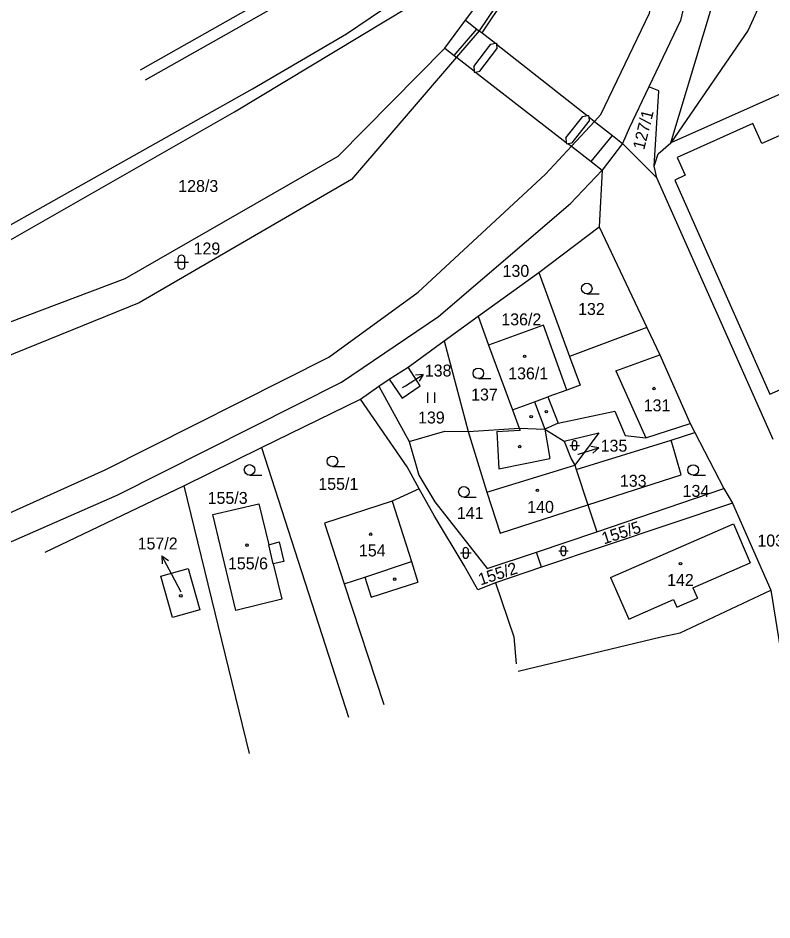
# Model space of a CAD drawing. Extents: x -783716 to -783033, y -1065203 to -1064697.
# Drawn here: x -783577.2 to -783469.9, y -1065203.3 to -1065075 of the extents above; entities that cross this region are included whole.
import ezdxf

# ---------------------------------------------------------------- set-up
doc = ezdxf.new("R2010")
doc.units = 0
for name, color, linetype in [('Budovy', 7, 'Continuous'), ('Doplňkové značky', 7, 'Continuous'), ('Doplňující texty', 7, 'Continuous'), ('Kultury', 7, 'Continuous'), ('Stromy_porost', 7, 'Continuous'), ('Značky IS', 7, 'Continuous')]:
    doc.layers.add(name, color=color, linetype=linetype)

msp = doc.modelspace()

# ---------------------------------------------------------------- linework, layer by layer
at = {"layer": 'Budovy'}
for p, q in [((-783540.15, -1065071.29), (-783559.84, -1065082.45)), ((-783482.97, -1065075.36), (-783487.46, -1065084.8)), ((-783455.41, -1065079.83), (-783484.32, -1065092.79)), ((-783487.46, -1065084.8), (-783490.25, -1065090.68)), ((-783490.25, -1065090.68), (-783491.22, -1065092.86)), ((-783491.22, -1065092.86), (-783494.09, -1065096.67)), ((-783486.32, -1065097.76), (-783491.22, -1065092.86)), ((-783486.32, -1065097.76), (-783486.71, -1065096.08)), ((-783494.09, -1065096.67), (-783494.53, -1065104.73)), ((-783469.78, -1065134.96), (-783486.32, -1065097.76)), ((-783503.12, -1065111.2), (-783494.53, -1065104.73)), ((-783494.53, -1065104.73), (-783487.76, -1065119.02)), ((-783511.74, -1065117.43), (-783503.12, -1065111.2)), ((-783503.12, -1065111.2), (-783498.74, -1065123.15)), ((-783516.56, -1065120.92), (-783511.74, -1065117.43)), ((-783511.74, -1065117.43), (-783510.28, -1065121.53)), ((-783487.76, -1065119.02), (-783498.74, -1065123.15)), ((-783521.71, -1065124.69), (-783516.56, -1065120.92)), ((-783516.56, -1065120.92), (-783513.18, -1065133.85)), ((-783524.38, -1065126.39), (-783521.71, -1065124.69)), ((-783525.85, -1065127.4), (-783524.38, -1065126.39)), ((-783528.47, -1065129.21), (-783525.85, -1065127.4)), ((-783525.85, -1065127.4), (-783521.55, -1065135.25)), ((-783542.54, -1065136.12), (-783528.47, -1065129.21)), ((-783513.18, -1065133.85), (-783505.89, -1065133.34)), ((-783505.89, -1065133.34), (-783502.25, -1065133.52)), ((-783500.34, -1065132.66), (-783502.25, -1065133.52)), ((-783481.58, -1065132.68), (-783480.9, -1065133.99)), ((-783502.25, -1065133.52), (-783499.53, -1065135.19)), ((-783480.9, -1065133.99), (-783476.78, -1065141.96)), ((-783553.59, -1065141.54), (-783542.54, -1065136.12)), ((-783542.54, -1065136.12), (-783530.17, -1065174.45)), ((-783573.32, -1065150.99), (-783553.59, -1065141.54)), ((-783553.59, -1065141.54), (-783544.3, -1065179.62)), ((-783494.85, -1065148.08), (-783476.78, -1065141.96)), ((-783476.78, -1065141.96), (-783475.54, -1065144.01)), ((-783475.54, -1065144.01), (-783502.74, -1065153.14)), ((-783496.14, -1065144.24), (-783494.85, -1065148.08)), ((-783475.54, -1065144.01), (-783470.12, -1065156.38)), ((-783503.46, -1065150.98), (-783494.85, -1065148.08)), ((-783502.74, -1065153.14), (-783503.46, -1065150.98)), ((-783502.74, -1065153.14), (-783509.29, -1065155.34))]:
    msp.add_line(p, q, dxfattribs=at)
for points in [[(-783586.68, -1065149.16), (-783564.78, -1065139.29), (-783532.97, -1065123.26), (-783520.29, -1065114.03), (-783502.16, -1065097.24), (-783498.48, -1065093.26), (-783495.21, -1065089.71), (-783494.31, -1065088.74), (-783487.35, -1065074.33), (-783482.56, -1065054.25), (-783479.58, -1065017.78), (-783475.47, -1064981.45), (-783469.34, -1064952.28), (-783461.55, -1064937.01), (-783445.96, -1064920.48), (-783433.11, -1064911.15), (-783418.04, -1064903.77), (-783403.59, -1064898.67), (-783393.97, -1064894.19), (-783364.93, -1064886.92), (-783332.97, -1064881.2)], [(-783416.55, -1064908), (-783430.48, -1064914.8), (-783443.35, -1064924.13), (-783457.58, -1064939.04), (-783464.9, -1064953.22), (-783471.03, -1064982.39), (-783475.1, -1065018.21), (-783477.98, -1065052.91), (-783478.07, -1065054.51), (-783482.97, -1065075.36)], [(-783607.85, -1065123.43), (-783546.39, -1065088.37), (-783521.44, -1065073.34), (-783511.77, -1065063.08), (-783506.35, -1065048.95), (-783502.14, -1065032.55), (-783497.09, -1065007.24), (-783492.53, -1064987.86)], [(-783484.32, -1065092.79), (-783477.5, -1065070.05), (-783471.02, -1065037.32)], [(-783467.47, -1065050.82), (-783467.56, -1065063.94), (-783473.33, -1065076.72), (-783484.32, -1065092.79)], [(-783504.59, -1065066.42), (-783511.59, -1065076.83), (-783514.83, -1065080.59), (-783529.78, -1065097.96), (-783559.97, -1065115.54), (-783579.36, -1065123.41), (-783592.85, -1065128.61), (-783597.17, -1065129.64), (-783598.62, -1065130.29), (-783638.54, -1065148.19)], [(-783580.95, -1065119.21), (-783561.96, -1065112.08), (-783531.67, -1065094.68), (-783516.49, -1065079.31), (-783513.55, -1065075.3), (-783512.37, -1065073.74), (-783504.59, -1065066.42)], [(-783486.71, -1065096.08), (-783486.05, -1065085.37), (-783487.46, -1065084.8)], [(-783453.34, -1065084.82), (-783463.36, -1065089.28), (-783464.48, -1065086.76), (-783468.77, -1065088.67), (-783467.65, -1065091.19), (-783471.41, -1065092.87), (-783472.69, -1065090.02), (-783483.45, -1065094.84), (-783482.3, -1065097.39), (-783483.76, -1065098.09), (-783470.24, -1065128.54), (-783467.23, -1065127.21), (-783466.55, -1065128.54), (-783460.33, -1065125.81), (-783460.98, -1065124.44), (-783457.93, -1065123.1), (-783461.31, -1065115.7), (-783433.81, -1065103.48), (-783436.82, -1065096.73), (-783436.47, -1065096.56)], [(-783486.71, -1065096.08), (-783486.12, -1065094.34), (-783484.32, -1065092.79)], [(-783714.74, -1065203.31), (-783709.33, -1065202.33), (-783678.96, -1065185.72), (-783654.5, -1065174.91), (-783629.71, -1065165.76), (-783589.13, -1065151.92), (-783581.73, -1065151.06), (-783562.99, -1065142.86), (-783531.18, -1065126.83), (-783517.38, -1065117.45), (-783498.6, -1065101.42), (-783494.09, -1065096.67)], [(-783499.13, -1065127.94), (-783502.45, -1065118.68), (-783510.28, -1065121.53)], [(-783487.76, -1065119.02), (-783485.91, -1065122.94), (-783481.58, -1065132.68)], [(-783510.28, -1065121.53), (-783506.84, -1065130.77), (-783505.89, -1065133.34)], [(-783498.74, -1065123.15), (-783497.24, -1065127.25), (-783499.13, -1065127.94)], [(-783524.38, -1065126.39), (-783522.56, -1065129.07), (-783520.01, -1065127.35), (-783521.71, -1065124.69)], [(-783499.13, -1065127.94), (-783501.84, -1065128.92), (-783500.34, -1065132.66)], [(-783520.12, -1065141.97), (-783521.86, -1065138.86), (-783528.47, -1065129.21)], [(-783500.34, -1065132.66), (-783492.31, -1065130.95), (-783490.82, -1065134.42), (-783487.88, -1065134.73), (-783481.58, -1065132.68)], [(-783521.55, -1065135.25), (-783516.5, -1065133.78), (-783513.18, -1065133.85)], [(-783513.18, -1065133.85), (-783510.53, -1065142.48), (-783508.62, -1065148.28), (-783496.14, -1065144.24)], [(-783499.53, -1065135.19), (-783494.6, -1065134), (-783497.98, -1065138.64)], [(-783496.14, -1065144.24), (-783482.86, -1065140), (-783484.28, -1065135.07), (-783480.9, -1065133.99)], [(-783521.55, -1065135.25), (-783520.17, -1065140.02), (-783517.91, -1065143.82), (-783510.44, -1065153.34), (-783503.46, -1065150.98)], [(-783499.53, -1065135.19), (-783498.49, -1065137.72), (-783497.98, -1065138.64)], [(-783497.98, -1065138.64), (-783497.82, -1065139.25), (-783496.14, -1065144.24)], [(-783520.12, -1065141.97), (-783523.98, -1065143.75), (-783533.59, -1065146.88), (-783530.8, -1065155.52), (-783525.15, -1065172.66)], [(-783509.29, -1065155.34), (-783511.8, -1065156.37), (-783513.75, -1065152.91), (-783517.96, -1065145.89), (-783520.12, -1065141.97)], [(-783539.37, -1065152.31), (-783540.88, -1065152.66), (-783539.67, -1065157.7), (-783546.23, -1065159.28), (-783549.48, -1065145.64), (-783542.92, -1065144.1), (-783541.52, -1065149.95), (-783540.06, -1065149.52), (-783539.37, -1065152.31)], [(-783552.99, -1065153.33), (-783551.32, -1065159.2), (-783555.21, -1065160.31), (-783556.86, -1065154.43), (-783552.99, -1065153.33)], [(-783509.29, -1065155.34), (-783506.65, -1065163.02), (-783506.34, -1065166.89)], [(-783506.07, -1065167.92), (-783485.73, -1065163.03), (-783483, -1065162.45), (-783470.12, -1065156.38)], [(-783470.12, -1065156.38), (-783468.61, -1065165.85), (-783468.3, -1065170.76)]]:
    msp.add_lwpolyline(points, dxfattribs=at)
at = {"layer": 'Doplňkové značky'}
for p, q in [((-783547.52, -1065077.32), (-783528.48, -1065066.44)), ((-783511.17, -1065077.1), (-783504.11, -1065066.56)), ((-783530.49, -1065077.27), (-783523.72, -1065072.69)), ((-783513.55, -1065075.3), (-783511.91, -1065076.58)), ((-783515.16, -1065080.33), (-783511.91, -1065076.58)), ((-783511.91, -1065076.58), (-783511.59, -1065076.83)), ((-783511.59, -1065076.83), (-783511.17, -1065077.1)), ((-783559.07, -1065083.82), (-783547.52, -1065077.32)), ((-783543.86, -1065085.11), (-783530.49, -1065077.27)), ((-783511.17, -1065077.1), (-783509.28, -1065078.6)), ((-783516.49, -1065079.31), (-783515.16, -1065080.33)), ((-783512.38, -1065081.91), (-783509.94, -1065078.71)), ((-783511.51, -1065082.59), (-783509.07, -1065079.39)), ((-783509.94, -1065078.71), (-783509.28, -1065078.6)), ((-783509.28, -1065078.6), (-783509.13, -1065078.57)), ((-783509.13, -1065078.57), (-783509.12, -1065078.72)), ((-783509.12, -1065078.72), (-783496.23, -1065088.9)), ((-783509.12, -1065078.72), (-783509.07, -1065079.39)), ((-783515.16, -1065080.33), (-783514.83, -1065080.59)), ((-783514.83, -1065080.59), (-783512.33, -1065082.53)), ((-783512.38, -1065081.91), (-783512.33, -1065082.53)), ((-783512.33, -1065082.53), (-783512.31, -1065082.73)), ((-783512.31, -1065082.73), (-783512.11, -1065082.7)), ((-783512.11, -1065082.7), (-783511.51, -1065082.59)), ((-783512.11, -1065082.7), (-783499.21, -1065092.7)), ((-783584.79, -1065108.09), (-783543.86, -1065085.11)), ((-783499.26, -1065092.08), (-783496.84, -1065089.01)), ((-783498.38, -1065092.76), (-783495.97, -1065089.69)), ((-783496.84, -1065089.01), (-783496.23, -1065088.9)), ((-783496.23, -1065088.9), (-783496.03, -1065088.87)), ((-783496.03, -1065088.87), (-783496.02, -1065089.07)), ((-783496.02, -1065089.07), (-783495.97, -1065089.69)), ((-783496.02, -1065089.07), (-783495.21, -1065089.71)), ((-783495.21, -1065089.71), (-783492.64, -1065091.74)), ((-783499.26, -1065092.08), (-783499.21, -1065092.7)), ((-783495.68, -1065095.43), (-783492.64, -1065091.74)), ((-783492.64, -1065091.74), (-783491.22, -1065092.86)), ((-783499.21, -1065092.7), (-783499.19, -1065092.9)), ((-783499.19, -1065092.9), (-783498.99, -1065092.87)), ((-783498.99, -1065092.87), (-783498.38, -1065092.76)), ((-783498.99, -1065092.87), (-783498.48, -1065093.26)), ((-783498.48, -1065093.26), (-783495.68, -1065095.43)), ((-783495.68, -1065095.43), (-783494.09, -1065096.67)), ((-783492.17, -1065125.21), (-783485.91, -1065122.94)), ((-783492.17, -1065125.21), (-783487.88, -1065134.73)), ((-783506.84, -1065130.77), (-783503.71, -1065129.61)), ((-783503.71, -1065129.61), (-783501.84, -1065128.92)), ((-783503.71, -1065129.61), (-783502.25, -1065133.52)), ((-783505.89, -1065133.34), (-783505.78, -1065133.66)), ((-783509.1, -1065133.83), (-783505.78, -1065133.66)), ((-783509.1, -1065133.83), (-783508.8, -1065139.15)), ((-783502.25, -1065133.52), (-783501.56, -1065137.65)), ((-783497.82, -1065139.25), (-783484.28, -1065135.07)), ((-783508.8, -1065139.15), (-783501.56, -1065137.65)), ((-783510.53, -1065142.48), (-783497.98, -1065138.64)), ((-783523.98, -1065143.75), (-783521.24, -1065152.32)), ((-783492.91, -1065154.6), (-783475.41, -1065146.96)), ((-783475.41, -1065146.96), (-783473.07, -1065152.53)), ((-783540.88, -1065152.66), (-783541.52, -1065149.95)), ((-783527.88, -1065154.54), (-783521.24, -1065152.32)), ((-783521.24, -1065152.32), (-783520.32, -1065155.25)), ((-783481.2, -1065156.05), (-783473.07, -1065152.53)), ((-783530.8, -1065155.52), (-783527.88, -1065154.54)), ((-783527.88, -1065154.54), (-783526.97, -1065157.41)), ((-783526.97, -1065157.41), (-783520.32, -1065155.25)), ((-783492.91, -1065154.6), (-783490.32, -1065160.53)), ((-783481.2, -1065156.05), (-783480.55, -1065157.54)), ((-783490.32, -1065160.53), (-783483.95, -1065157.74)), ((-783483.95, -1065157.74), (-783483.48, -1065158.81)), ((-783483.48, -1065158.81), (-783480.55, -1065157.54))]:
    msp.add_line(p, q, dxfattribs=at)
at = {"layer": 'Doplňující texty'}
for centre in [(-783505.14, -1065123.13), (-783486.72, -1065127.72), (-783502.05, -1065131.01), (-783504.2, -1065131.71), (-783505.83, -1065135.97), (-783503.32, -1065142.2), (-783527.03, -1065148.44), (-783544.62, -1065150), (-783482.96, -1065152.64), (-783523.62, -1065154.83), (-783554.04, -1065157.2)]:
    msp.add_circle(centre, 0.175, dxfattribs=at)
at = {"layer": 'Kultury'}
for p, q in [((-783554.95, -1065109.75), (-783552.95, -1065109.75)), ((-783554.45, -1065109.25), (-783554.45, -1065110.25)), ((-783553.45, -1065110.25), (-783553.45, -1065109.25)), ((-783496.29, -1065114.24), (-783494.54, -1065114.24)), ((-783511.71, -1065126.3), (-783509.96, -1065126.3)), ((-783518.92, -1065129.76), (-783518.92, -1065128.26)), ((-783517.92, -1065129.76), (-783517.92, -1065128.26)), ((-783498.69, -1065135.8), (-783497.35, -1065135.8)), ((-783498.35, -1065135.47), (-783498.35, -1065136.14)), ((-783497.69, -1065136.14), (-783497.69, -1065135.47)), ((-783532.47, -1065138.83), (-783530.72, -1065138.83)), ((-783544.26, -1065140.04), (-783542.51, -1065140.04)), ((-783481.16, -1065140.05), (-783479.41, -1065140.05)), ((-783513.77, -1065143.16), (-783512.02, -1065143.16)), ((-783514.27, -1065151.1), (-783512.75, -1065151.1)), ((-783513.89, -1065150.72), (-783513.89, -1065151.48)), ((-783513.13, -1065151.48), (-783513.13, -1065150.72)), ((-783500.29, -1065150.81), (-783498.95, -1065150.81)), ((-783499.96, -1065150.48), (-783499.96, -1065151.15)), ((-783499.29, -1065151.15), (-783499.29, -1065150.48))]:
    msp.add_line(p, q, dxfattribs=at)
for centre in [(-783496.29, -1065113.49), (-783511.71, -1065125.55), (-783544.26, -1065139.29), (-783532.47, -1065138.08), (-783481.16, -1065139.3), (-783513.77, -1065142.41)]:
    msp.add_circle(centre, 0.75, dxfattribs=at)
for centre, radius, start, end in [((-783553.95, -1065109.25), 0.5, 0, 180), ((-783553.95, -1065110.25), 0.5, 180, 359.9879), ((-783498.02, -1065135.47), 0.335, 0, 180), ((-783498.02, -1065136.14), 0.335, 180, 359.9879), ((-783499.62, -1065150.48), 0.335, 0, 180), ((-783513.51, -1065150.72), 0.38, 0, 180), ((-783499.62, -1065151.15), 0.335, 180, 359.9879), ((-783513.51, -1065151.48), 0.38, 180, 359.9879)]:
    msp.add_arc(centre, radius, start, end, dxfattribs=at)
at = {"layer": 'Stromy_porost'}
for p, q in [((-783522.09, -1065127.31), (-783519.55, -1065125.72)), ((-783519.55, -1065125.72), (-783520.66, -1065125.83)), ((-783519.55, -1065125.72), (-783520.13, -1065126.68)), ((-783522.49, -1065127.56), (-783522.09, -1065127.31)), ((-783494.6, -1065136.15), (-783495.7, -1065135.97)), ((-783497.57, -1065137.06), (-783497.47, -1065137.03)), ((-783497.47, -1065137.03), (-783494.6, -1065136.15)), ((-783494.6, -1065136.15), (-783495.41, -1065136.92)), ((-783555.31, -1065154.17), (-783556.72, -1065151.52)), ((-783556.72, -1065151.52), (-783555.81, -1065152.17)), ((-783556.72, -1065151.52), (-783556.69, -1065152.64)), ((-783553.97, -1065156.69), (-783555.31, -1065154.17))]:
    msp.add_line(p, q, dxfattribs=at)

# ---------------------------------------------------------------- texts
at = {"layer": 'Značky IS'}
for s, rotation, p in [('127/1', 76, (-783488.13, -1065093.86)), ('155/5', 18, (-783493.85, -1065149.9)), ('155/2', 18, (-783511.41, -1065155.74))]:
    msp.add_text(s, height=1.7, rotation=rotation, dxfattribs=at).set_placement(p)
for s, p in [('128/3', (-783554.4, -1065099.76)), ('129', (-783552.22, -1065108.65)), ('130', (-783508.27, -1065111.83)), ('132', (-783497.53, -1065117.25)), ('136/2', (-783508.45, -1065118.73)), ('138', (-783519.33, -1065126.01)), ('136/1', (-783507.47, -1065126.41)), ('137', (-783512.74, -1065129.42)), ('131', (-783488.19, -1065130.96)), ('139', (-783520.29, -1065132.69)), ('135', (-783494.32, -1065136.7)), ('155/1', (-783534.48, -1065142.13)), ('133', (-783491.58, -1065141.69)), ('155/3', (-783550.22, -1065144.13)), ('134', (-783482.66, -1065143.13)), ('140', (-783504.76, -1065145.4)), ('141', (-783514.77, -1065146.27)), ('157/2', (-783560.18, -1065150.61)), ('103/2', (-783472.02, -1065150.19)), ('154', (-783528.7, -1065151.6)), ('155/6', (-783547.33, -1065153.44)), ('142', (-783484.87, -1065155.8))]:
    msp.add_text(s, height=1.7, dxfattribs=at).set_placement(p)

doc.saveas('drawing.dxf')
